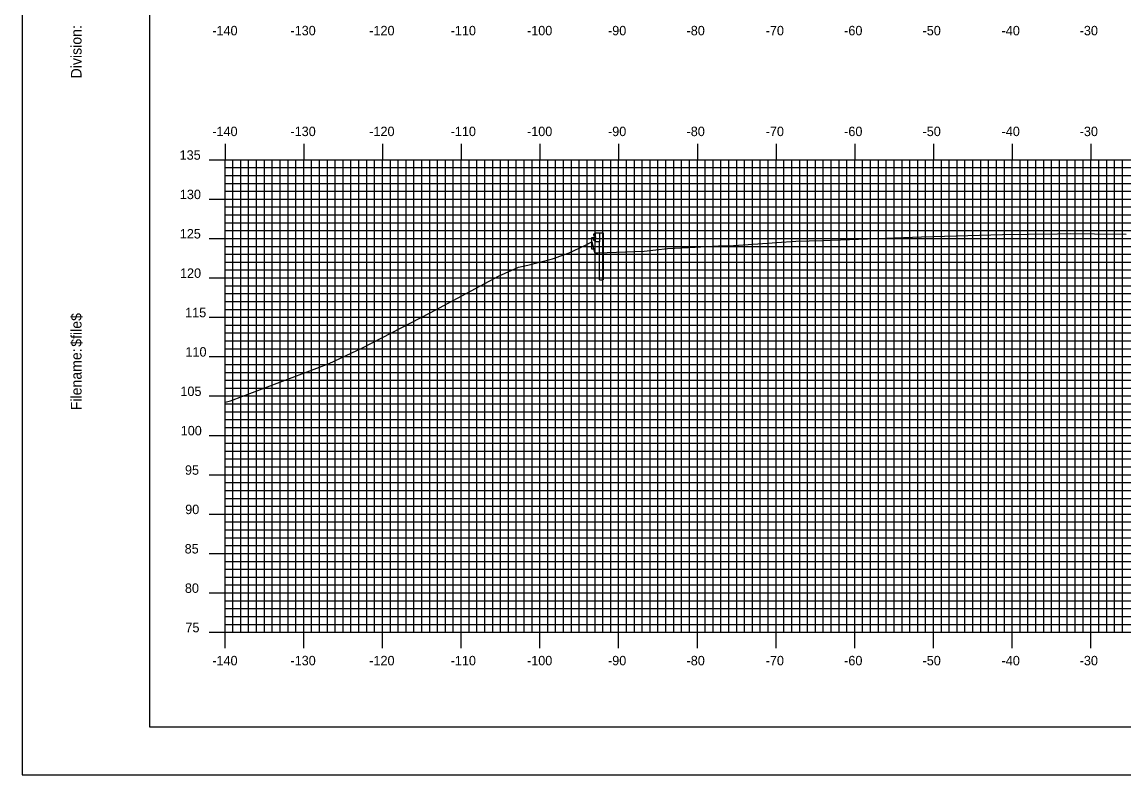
# Model space of a CAD drawing. Extents: x 857658 to 858001, y 364366 to 364586.
# Drawn here: x 857658.1 to 857798, y 364365.7 to 364461.3 of the extents above; entities that cross this region are included whole.
import ezdxf

# ---------------------------------------------------------------- set-up
doc = ezdxf.new("R2010")
doc.units = 0
for name, color, linetype in [('BORDER', 7, 'Continuous'), ('H_V ANNOTATION', 7, 'Continuous'), ('M_Roadway_Centerline', 7, 'Continuous'), ('MAJOR', 7, 'Continuous'), ('MINOR', 7, 'Continuous'), ('PLOT BOUNDARY', 7, 'Continuous'), ('S_Curb_Type_1', 7, 'Continuous'), ('S_Guardrail_Beam', 7, 'Continuous'), ('S_Roadway_Centerline', 7, 'Continuous')]:
    doc.layers.add(name, color=color, linetype=linetype)

msp = doc.modelspace()

# ---------------------------------------------------------------- linework, layer by layer
at = {"layer": 'BORDER'}
msp.add_lwpolyline([(857674.25, 364371.79), (857994.25, 364371.79), (857994.25, 364581.79), (857674.25, 364581.79)], close=True, dxfattribs=at)
at = {"layer": 'MAJOR'}
for p, q in [((857683.85, 364445.79), (857683.85, 364443.79)), ((857693.85, 364445.79), (857693.85, 364443.79)), ((857703.85, 364445.79), (857703.85, 364443.79)), ((857713.85, 364445.79), (857713.85, 364443.79)), ((857723.85, 364445.79), (857723.85, 364443.79)), ((857733.85, 364445.79), (857733.85, 364443.79)), ((857743.85, 364445.79), (857743.85, 364443.79)), ((857753.85, 364445.79), (857753.85, 364443.79)), ((857763.85, 364445.79), (857763.85, 364443.79)), ((857773.85, 364445.79), (857773.85, 364443.79)), ((857783.85, 364445.79), (857783.85, 364443.79)), ((857793.85, 364445.79), (857793.85, 364443.79)), ((857681.84, 364443.79), (857683.85, 364443.79)), ((857683.85, 364443.79), (857963.85, 364443.79)), ((857683.85, 364383.79), (857683.85, 364443.79)), ((857683.85, 364383.79), (857683.85, 364443.79)), ((857683.85, 364443.79), (857963.85, 364443.79)), ((857693.85, 364383.79), (857693.85, 364443.79)), ((857703.85, 364383.79), (857703.85, 364443.79)), ((857713.85, 364383.79), (857713.85, 364443.79)), ((857723.85, 364383.79), (857723.85, 364443.79)), ((857733.85, 364383.79), (857733.85, 364443.79)), ((857743.85, 364383.79), (857743.85, 364443.79)), ((857753.85, 364383.79), (857753.85, 364443.79)), ((857763.85, 364383.79), (857763.85, 364443.79)), ((857773.85, 364383.79), (857773.85, 364443.79)), ((857783.85, 364383.79), (857783.85, 364443.79)), ((857793.85, 364383.79), (857793.85, 364443.79)), ((857681.84, 364438.79), (857683.85, 364438.79)), ((857683.85, 364438.79), (857963.85, 364438.79)), ((857681.84, 364433.79), (857683.85, 364433.79)), ((857683.85, 364433.79), (857963.85, 364433.79)), ((857681.84, 364428.79), (857683.85, 364428.79)), ((857683.85, 364428.79), (857963.85, 364428.79)), ((857681.84, 364423.79), (857683.85, 364423.79)), ((857683.85, 364423.79), (857963.85, 364423.79)), ((857681.84, 364418.79), (857683.85, 364418.79)), ((857683.85, 364418.79), (857963.85, 364418.79)), ((857681.84, 364413.79), (857683.85, 364413.79)), ((857683.85, 364413.79), (857963.85, 364413.79)), ((857681.84, 364408.79), (857683.85, 364408.79)), ((857683.85, 364408.79), (857963.85, 364408.79)), ((857681.84, 364403.79), (857683.85, 364403.79)), ((857683.85, 364403.79), (857963.85, 364403.79)), ((857681.84, 364398.79), (857683.85, 364398.79)), ((857683.85, 364398.79), (857963.85, 364398.79)), ((857681.84, 364393.79), (857683.85, 364393.79)), ((857683.85, 364393.79), (857963.85, 364393.79)), ((857681.84, 364388.79), (857683.85, 364388.79)), ((857683.85, 364388.79), (857963.85, 364388.79)), ((857681.84, 364383.79), (857683.85, 364383.79)), ((857683.85, 364383.79), (857963.85, 364383.79)), ((857683.85, 364383.79), (857963.85, 364383.79)), ((857683.85, 364381.78), (857683.85, 364383.79)), ((857693.85, 364381.78), (857693.85, 364383.79)), ((857703.85, 364381.78), (857703.85, 364383.79)), ((857713.85, 364381.78), (857713.85, 364383.79)), ((857723.85, 364381.78), (857723.85, 364383.79)), ((857733.85, 364381.78), (857733.85, 364383.79)), ((857743.85, 364381.78), (857743.85, 364383.79)), ((857753.85, 364381.78), (857753.85, 364383.79)), ((857763.85, 364381.78), (857763.85, 364383.79)), ((857773.85, 364381.78), (857773.85, 364383.79)), ((857783.85, 364381.78), (857783.85, 364383.79)), ((857793.85, 364381.78), (857793.85, 364383.79))]:
    msp.add_line(p, q, dxfattribs=at)
at = {"layer": 'MINOR'}
for p, q in [((857684.85, 364383.79), (857684.85, 364443.79)), ((857685.85, 364383.79), (857685.85, 364443.79)), ((857686.85, 364383.79), (857686.85, 364443.79)), ((857687.85, 364383.79), (857687.85, 364443.79)), ((857688.85, 364383.79), (857688.85, 364443.79)), ((857689.85, 364383.79), (857689.85, 364443.79)), ((857690.85, 364383.79), (857690.85, 364443.79)), ((857691.85, 364383.79), (857691.85, 364443.79)), ((857692.85, 364383.79), (857692.85, 364443.79)), ((857694.85, 364383.79), (857694.85, 364443.79)), ((857695.85, 364383.79), (857695.85, 364443.79)), ((857696.85, 364383.79), (857696.85, 364443.79)), ((857697.85, 364383.79), (857697.85, 364443.79)), ((857698.85, 364383.79), (857698.85, 364443.79)), ((857699.85, 364383.79), (857699.85, 364443.79)), ((857700.85, 364383.79), (857700.85, 364443.79)), ((857701.85, 364383.79), (857701.85, 364443.79)), ((857702.85, 364383.79), (857702.85, 364443.79)), ((857704.85, 364383.79), (857704.85, 364443.79)), ((857705.85, 364383.79), (857705.85, 364443.79)), ((857706.85, 364383.79), (857706.85, 364443.79)), ((857707.85, 364383.79), (857707.85, 364443.79)), ((857708.85, 364383.79), (857708.85, 364443.79)), ((857709.85, 364383.79), (857709.85, 364443.79)), ((857710.85, 364383.79), (857710.85, 364443.79)), ((857711.85, 364383.79), (857711.85, 364443.79)), ((857712.85, 364383.79), (857712.85, 364443.79)), ((857714.85, 364383.79), (857714.85, 364443.79)), ((857715.85, 364383.79), (857715.85, 364443.79)), ((857716.85, 364383.79), (857716.85, 364443.79)), ((857717.85, 364383.79), (857717.85, 364443.79)), ((857718.85, 364383.79), (857718.85, 364443.79)), ((857719.85, 364383.79), (857719.85, 364443.79)), ((857720.85, 364383.79), (857720.85, 364443.79)), ((857721.85, 364383.79), (857721.85, 364443.79)), ((857722.85, 364383.79), (857722.85, 364443.79)), ((857724.85, 364383.79), (857724.85, 364443.79)), ((857725.85, 364383.79), (857725.85, 364443.79)), ((857726.85, 364383.79), (857726.85, 364443.79)), ((857727.85, 364383.79), (857727.85, 364443.79)), ((857728.85, 364383.79), (857728.85, 364443.79)), ((857729.85, 364383.79), (857729.85, 364443.79)), ((857730.85, 364383.79), (857730.85, 364443.79)), ((857731.85, 364383.79), (857731.85, 364443.79)), ((857732.85, 364383.79), (857732.85, 364443.79)), ((857734.85, 364383.79), (857734.85, 364443.79)), ((857735.85, 364383.79), (857735.85, 364443.79)), ((857736.85, 364383.79), (857736.85, 364443.79)), ((857737.85, 364383.79), (857737.85, 364443.79)), ((857738.85, 364383.79), (857738.85, 364443.79)), ((857739.85, 364383.79), (857739.85, 364443.79)), ((857740.85, 364383.79), (857740.85, 364443.79)), ((857741.85, 364383.79), (857741.85, 364443.79)), ((857742.85, 364383.79), (857742.85, 364443.79)), ((857744.85, 364383.79), (857744.85, 364443.79)), ((857745.85, 364383.79), (857745.85, 364443.79)), ((857746.85, 364383.79), (857746.85, 364443.79)), ((857747.85, 364383.79), (857747.85, 364443.79)), ((857748.85, 364383.79), (857748.85, 364443.79)), ((857749.85, 364383.79), (857749.85, 364443.79)), ((857750.85, 364383.79), (857750.85, 364443.79)), ((857751.85, 364383.79), (857751.85, 364443.79)), ((857752.85, 364383.79), (857752.85, 364443.79)), ((857754.85, 364383.79), (857754.85, 364443.79)), ((857755.85, 364383.79), (857755.85, 364443.79)), ((857756.85, 364383.79), (857756.85, 364443.79)), ((857757.85, 364383.79), (857757.85, 364443.79)), ((857758.85, 364383.79), (857758.85, 364443.79)), ((857759.85, 364383.79), (857759.85, 364443.79)), ((857760.85, 364383.79), (857760.85, 364443.79)), ((857761.85, 364383.79), (857761.85, 364443.79)), ((857762.85, 364383.79), (857762.85, 364443.79)), ((857764.85, 364383.79), (857764.85, 364443.79)), ((857765.85, 364383.79), (857765.85, 364443.79)), ((857766.85, 364383.79), (857766.85, 364443.79)), ((857767.85, 364383.79), (857767.85, 364443.79)), ((857768.85, 364383.79), (857768.85, 364443.79)), ((857769.85, 364383.79), (857769.85, 364443.79)), ((857770.85, 364383.79), (857770.85, 364443.79)), ((857771.85, 364383.79), (857771.85, 364443.79)), ((857772.85, 364383.79), (857772.85, 364443.79)), ((857774.85, 364383.79), (857774.85, 364443.79)), ((857775.85, 364383.79), (857775.85, 364443.79)), ((857776.85, 364383.79), (857776.85, 364443.79)), ((857777.85, 364383.79), (857777.85, 364443.79)), ((857778.85, 364383.79), (857778.85, 364443.79)), ((857779.85, 364383.79), (857779.85, 364443.79)), ((857780.85, 364383.79), (857780.85, 364443.79)), ((857781.85, 364383.79), (857781.85, 364443.79)), ((857782.85, 364383.79), (857782.85, 364443.79)), ((857784.85, 364383.79), (857784.85, 364443.79)), ((857785.85, 364383.79), (857785.85, 364443.79)), ((857786.85, 364383.79), (857786.85, 364443.79)), ((857787.85, 364383.79), (857787.85, 364443.79)), ((857788.85, 364383.79), (857788.85, 364443.79)), ((857789.85, 364383.79), (857789.85, 364443.79)), ((857790.85, 364383.79), (857790.85, 364443.79)), ((857791.85, 364383.79), (857791.85, 364443.79)), ((857792.85, 364383.79), (857792.85, 364443.79)), ((857794.85, 364383.79), (857794.85, 364443.79)), ((857795.85, 364383.79), (857795.85, 364443.79)), ((857796.85, 364383.79), (857796.85, 364443.79)), ((857797.85, 364383.79), (857797.85, 364443.79)), ((857683.85, 364442.79), (857963.85, 364442.79)), ((857683.85, 364442.79), (857685.85, 364442.79)), ((857683.85, 364441.79), (857963.85, 364441.79)), ((857683.85, 364441.79), (857685.85, 364441.79)), ((857683.85, 364440.79), (857963.85, 364440.79)), ((857683.85, 364440.79), (857685.85, 364440.79)), ((857683.85, 364439.79), (857963.85, 364439.79)), ((857683.85, 364439.79), (857685.85, 364439.79)), ((857683.85, 364437.79), (857963.85, 364437.79)), ((857683.85, 364437.79), (857685.85, 364437.79)), ((857683.85, 364436.79), (857963.85, 364436.79)), ((857683.85, 364436.79), (857685.85, 364436.79)), ((857683.85, 364435.79), (857963.85, 364435.79)), ((857683.85, 364435.79), (857685.85, 364435.79)), ((857683.85, 364434.79), (857963.85, 364434.79)), ((857683.85, 364434.79), (857685.85, 364434.79)), ((857683.85, 364432.79), (857963.85, 364432.79)), ((857683.85, 364432.79), (857685.85, 364432.79)), ((857683.85, 364431.79), (857963.85, 364431.79)), ((857683.85, 364431.79), (857685.85, 364431.79)), ((857683.85, 364430.79), (857963.85, 364430.79)), ((857683.85, 364430.79), (857685.85, 364430.79)), ((857683.85, 364429.79), (857963.85, 364429.79)), ((857683.85, 364429.79), (857685.85, 364429.79)), ((857683.85, 364427.79), (857963.85, 364427.79)), ((857683.85, 364427.79), (857685.85, 364427.79)), ((857683.85, 364426.79), (857963.85, 364426.79)), ((857683.85, 364426.79), (857685.85, 364426.79)), ((857683.85, 364425.79), (857963.85, 364425.79)), ((857683.85, 364425.79), (857685.85, 364425.79)), ((857683.85, 364424.79), (857963.85, 364424.79)), ((857683.85, 364424.79), (857685.85, 364424.79)), ((857683.85, 364422.79), (857963.85, 364422.79)), ((857683.85, 364422.79), (857685.85, 364422.79)), ((857683.85, 364421.79), (857963.85, 364421.79)), ((857683.85, 364421.79), (857685.85, 364421.79)), ((857683.85, 364420.79), (857963.85, 364420.79)), ((857683.85, 364420.79), (857685.85, 364420.79)), ((857683.85, 364419.79), (857963.85, 364419.79)), ((857683.85, 364419.79), (857685.85, 364419.79)), ((857683.85, 364417.79), (857963.85, 364417.79)), ((857683.85, 364417.79), (857685.85, 364417.79)), ((857683.85, 364416.79), (857963.85, 364416.79)), ((857683.85, 364416.79), (857685.85, 364416.79)), ((857683.85, 364415.79), (857963.85, 364415.79)), ((857683.85, 364415.79), (857685.85, 364415.79)), ((857683.85, 364414.79), (857963.85, 364414.79)), ((857683.85, 364414.79), (857685.85, 364414.79)), ((857683.85, 364412.79), (857963.85, 364412.79)), ((857683.85, 364412.79), (857685.85, 364412.79)), ((857683.85, 364411.79), (857963.85, 364411.79)), ((857683.85, 364411.79), (857685.85, 364411.79)), ((857683.85, 364410.79), (857963.85, 364410.79)), ((857683.85, 364410.79), (857685.85, 364410.79)), ((857683.85, 364409.79), (857963.85, 364409.79)), ((857683.85, 364409.79), (857685.85, 364409.79)), ((857683.85, 364407.79), (857963.85, 364407.79)), ((857683.85, 364407.79), (857685.85, 364407.79)), ((857683.85, 364406.79), (857963.85, 364406.79)), ((857683.85, 364406.79), (857685.85, 364406.79)), ((857683.85, 364405.79), (857963.85, 364405.79)), ((857683.85, 364405.79), (857685.85, 364405.79)), ((857683.85, 364404.79), (857963.85, 364404.79)), ((857683.85, 364404.79), (857685.85, 364404.79)), ((857683.85, 364402.79), (857963.85, 364402.79)), ((857683.85, 364402.79), (857685.85, 364402.79)), ((857683.85, 364401.79), (857963.85, 364401.79)), ((857683.85, 364401.79), (857685.85, 364401.79)), ((857683.85, 364400.79), (857963.85, 364400.79)), ((857683.85, 364400.79), (857685.85, 364400.79)), ((857683.85, 364399.79), (857963.85, 364399.79)), ((857683.85, 364399.79), (857685.85, 364399.79)), ((857683.85, 364397.79), (857963.85, 364397.79)), ((857683.85, 364397.79), (857685.85, 364397.79)), ((857683.85, 364396.79), (857963.85, 364396.79)), ((857683.85, 364396.79), (857685.85, 364396.79)), ((857683.85, 364395.79), (857963.85, 364395.79)), ((857683.85, 364395.79), (857685.85, 364395.79)), ((857683.85, 364394.79), (857963.85, 364394.79)), ((857683.85, 364394.79), (857685.85, 364394.79)), ((857683.85, 364392.79), (857963.85, 364392.79)), ((857683.85, 364392.79), (857685.85, 364392.79)), ((857683.85, 364391.79), (857963.85, 364391.79)), ((857683.85, 364391.79), (857685.85, 364391.79)), ((857683.85, 364390.79), (857963.85, 364390.79)), ((857683.85, 364390.79), (857685.85, 364390.79)), ((857683.85, 364389.79), (857963.85, 364389.79)), ((857683.85, 364389.79), (857685.85, 364389.79)), ((857683.85, 364387.79), (857963.85, 364387.79)), ((857683.85, 364387.79), (857685.85, 364387.79)), ((857683.85, 364386.79), (857963.85, 364386.79)), ((857683.85, 364386.79), (857685.85, 364386.79)), ((857683.85, 364385.79), (857963.85, 364385.79)), ((857683.85, 364385.79), (857685.85, 364385.79)), ((857683.85, 364384.79), (857963.85, 364384.79)), ((857683.85, 364384.79), (857685.85, 364384.79))]:
    msp.add_line(p, q, dxfattribs=at)
at = {"layer": 'PLOT BOUNDARY'}
msp.add_lwpolyline([(857658.06, 364365.67), (857998.06, 364365.67), (857998.06, 364585.67), (857658.06, 364585.67)], close=True, dxfattribs=at)
at = {"layer": 'S_Curb_Type_1'}
msp.add_lwpolyline([(857730.43, 364433.93), (857730.84, 364433.93), (857730.84, 364432.43), (857730.43, 364432.43)], close=True, dxfattribs=at)
msp.add_lwpolyline([(857730.43, 364433.93), (857730.84, 364433.93), (857730.84, 364432.43), (857730.43, 364432.43)], close=True, dxfattribs=at)
at = {"layer": 'S_Guardrail_Beam'}
for p, q in [((857730.82, 364434.44), (857730.68, 364434.34)), ((857730.82, 364434.44), (857730.68, 364434.34)), ((857730.68, 364434.19), (857730.88, 364434.06)), ((857730.68, 364434.19), (857730.88, 364434.06)), ((857730.88, 364433.84), (857730.68, 364433.7)), ((857730.88, 364433.84), (857730.68, 364433.7)), ((857730.92, 364434.46), (857730.84, 364434.44)), ((857730.92, 364434.46), (857730.84, 364434.44)), ((857730.91, 364433.99), (857730.91, 364433.9)), ((857730.91, 364433.99), (857730.91, 364433.9)), ((857730.92, 364434.53), (857731.41, 364434.53)), ((857730.92, 364433.37), (857730.92, 364434.53)), ((857730.92, 364434.53), (857731.41, 364434.53)), ((857730.92, 364433.37), (857730.92, 364434.53)), ((857731.41, 364434.53), (857731.9, 364434.53)), ((857731.41, 364434.53), (857731.41, 364433.37)), ((857731.41, 364434.53), (857731.9, 364434.53)), ((857731.41, 364434.53), (857731.41, 364433.37)), ((857731.9, 364434.53), (857731.9, 364428.53)), ((857731.9, 364434.53), (857731.9, 364428.53)), ((857730.68, 364433.56), (857730.82, 364433.46)), ((857730.68, 364433.56), (857730.82, 364433.46)), ((857730.84, 364433.45), (857730.92, 364433.44)), ((857730.84, 364433.45), (857730.92, 364433.44)), ((857731.41, 364433.37), (857730.92, 364433.37)), ((857731.41, 364433.37), (857730.92, 364433.37)), ((857731.41, 364428.53), (857731.41, 364433.37)), ((857731.41, 364428.53), (857731.41, 364433.37)), ((857731.41, 364428.53), (857731.9, 364428.53)), ((857731.41, 364428.53), (857731.9, 364428.53))]:
    msp.add_line(p, q, dxfattribs=at)
for centre, major_axis, start_param, end_param in [((857730.73, 364434.27), (-0.0877, 0), 5.323254, 7.243116), ((857730.73, 364434.27), (-0.0877, 0), 5.323254, 7.243116), ((857730.73, 364433.63), (-0.0877, 0), 5.323254, 7.243116), ((857730.73, 364433.63), (-0.0877, 0), 5.323254, 7.243116), ((857730.85, 364434.4), (-0.0417, 0), 4.886922, 5.323254), ((857730.85, 364434.4), (-0.0417, 0), 4.886922, 5.323254), ((857730.83, 364433.99), (0.0789, 0), 0, 0.959931), ((857730.83, 364433.99), (0.0789, 0), 0, 0.959931), ((857730.83, 364433.9), (0.0789, 0), 5.323254, 6.283185), ((857730.83, 364433.9), (0.0789, 0), 5.323254, 6.283185), ((857730.85, 364433.49), (-0.0417, 0), 0.959931, 1.396263), ((857730.85, 364433.49), (-0.0417, 0), 0.959931, 1.396263)]:
    msp.add_ellipse(centre, major_axis=major_axis, ratio=0.995501, start_param=start_param, end_param=end_param, dxfattribs=at)
at = {"layer": 'S_Roadway_Centerline'}
msp.add_lwpolyline([(857683.85, 364413.02), (857684.56, 364413.16), (857697.08, 364417.92), (857701.31, 364419.92), (857709.92, 364424.34), (857718.6, 364428.99), (857721.14, 364430.16), (857722.32, 364430.41), (857725.46, 364431.2), (857727.57, 364431.98), (857729.56, 364432.92), (857730.43, 364433.35), (857730.48, 364433.25), (857730.8, 364431.95), (857731.21, 364431.95), (857737.08, 364432.16), (857737.1, 364432.16), (857740.04, 364432.5), (857743.59, 364432.69), (857746.53, 364432.84), (857748.44, 364432.92), (857751.54, 364433.13), (857756.35, 364433.43), (857759.73, 364433.54), (857772.31, 364434.02), (857782.61, 364434.28), (857785.93, 364434.34), (857789.61, 364434.37), (857791.24, 364434.41), (857794.32, 364434.37), (857798.32, 364434.32)], dxfattribs=at)

# ---------------------------------------------------------------- texts
at = {"layer": 'BORDER'}
for s, p in [('Division:', (857665.62, 364454.12)), ('$file$', (857665.62, 364420.04)), ('Filename:', (857665.62, 364411.98))]:
    msp.add_text(s, height=1.339, rotation=90, dxfattribs=at).set_placement(p)
at = {"layer": 'H_V ANNOTATION'}
for s, p in [('-140', (857682.23, 364459.59)), ('-130', (857692.16, 364459.59)), ('-120', (857702.17, 364459.59)), ('-110', (857712.51, 364459.59)), ('-100', (857722.21, 364459.59)), ('-90', (857732.5, 364459.59)), ('-80', (857742.48, 364459.59)), ('-70', (857752.53, 364459.59)), ('-60', (857762.5, 364459.59)), ('-50', (857772.46, 364459.59)), ('-40', (857782.5, 364459.59)), ('-30', (857792.42, 364459.59)), ('-140', (857682.23, 364446.79)), ('-130', (857692.16, 364446.79)), ('-120', (857702.17, 364446.79)), ('-110', (857712.51, 364446.79)), ('-100', (857722.21, 364446.79)), ('-90', (857732.5, 364446.79)), ('-80', (857742.48, 364446.79)), ('-70', (857752.53, 364446.79)), ('-60', (857762.5, 364446.79)), ('-50', (857772.46, 364446.79)), ('-40', (857782.5, 364446.79)), ('-30', (857792.42, 364446.79)), ('135', (857678.08, 364443.79)), ('130', (857678.11, 364438.79)), ('125', (857678.1, 364433.79)), ('120', (857678.13, 364428.79)), ('115', (857678.78, 364423.79)), ('110', (857678.82, 364418.79)), ('105', (857678.18, 364413.79)), ('100', (857678.22, 364408.79)), ('95', (857678.76, 364403.79)), ('90', (857678.79, 364398.79)), ('85', (857678.72, 364393.79)), ('80', (857678.75, 364388.79)), ('75', (857678.82, 364383.79)), ('-140', (857682.23, 364379.59)), ('-130', (857692.16, 364379.59)), ('-120', (857702.17, 364379.59)), ('-110', (857712.51, 364379.59)), ('-100', (857722.21, 364379.59)), ('-90', (857732.5, 364379.59)), ('-80', (857742.48, 364379.59)), ('-70', (857752.53, 364379.59)), ('-60', (857762.5, 364379.59)), ('-50', (857772.46, 364379.59)), ('-40', (857782.5, 364379.59)), ('-30', (857792.42, 364379.59))]:
    msp.add_text(s, height=1.2, dxfattribs=at).set_placement(p)
at = {"layer": 'M_Roadway_Centerline'}
for s, p in [('C', (857791.23, 364434.41)), ('L', (857791.24, 364434.4)), ('C', (857748.43, 364432.92)), ('L', (857748.44, 364432.91))]:
    msp.add_text(s, height=0.0146, dxfattribs=at).set_placement(p)
at = {"layer": 'MAJOR'}
msp.add_text('-', height=0.012, dxfattribs=at).set_placement((857683.84, 364383.79))

doc.saveas('drawing.dxf')
